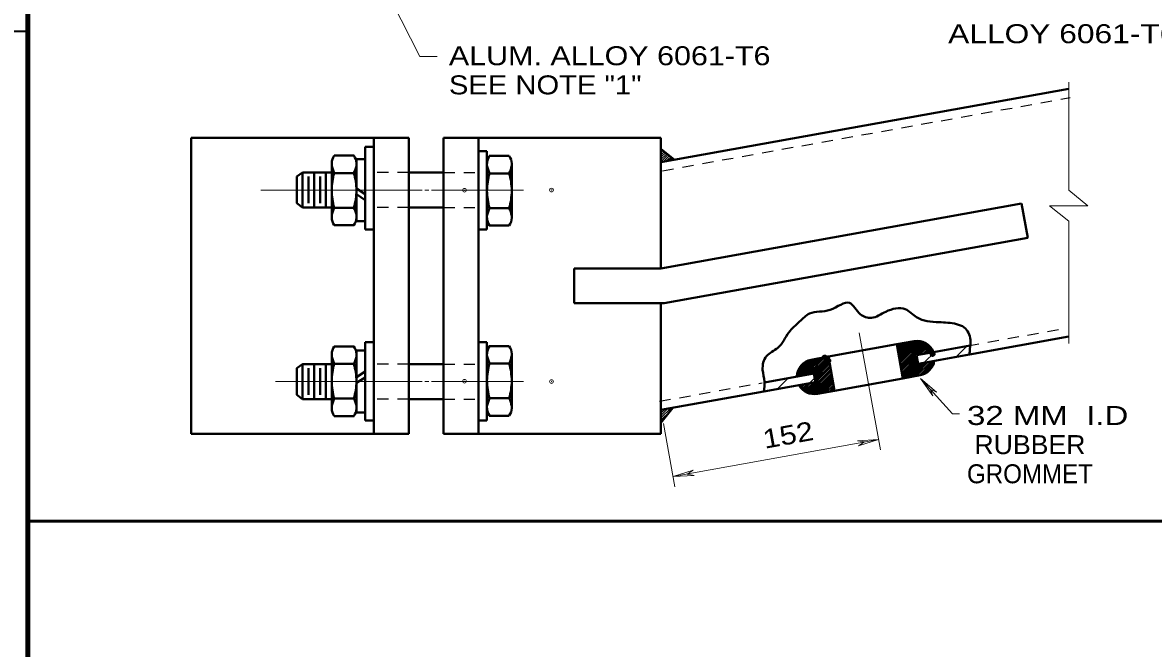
# Model space of a CAD drawing. Extents: x 312583 to 312854, y 144419 to 144597.
# Drawn here: x 312616.3 to 312661.58, y 144463.41 to 144488.46 of the extents above; entities that cross this region are included whole.
import ezdxf

# ---------------------------------------------------------------- set-up
doc = ezdxf.new("R2010")
doc.units = 0
doc.header["$LTSCALE"] = 0.3
doc.header["$PDMODE"] = 32
doc.header["$PDSIZE"] = 0.15
doc.linetypes.add('SHORT_DASHED', pattern=[2.7, 1.5, -1.2])
doc.layers.add('1', color=7, linetype='Continuous', lineweight=35)
doc.layers.add('2', color=7, linetype='Continuous', lineweight=13)

msp = doc.modelspace()

# ---------------------------------------------------------------- linework, layer by layer
at = {"layer": '1', "lineweight": 13}
for p, q in [((312658.1938, 144486.0803), (312658.1938, 144481.7486)), ((312658.1938, 144480.5066), (312658.1938, 144475.6153)), ((312652.4055, 144474.8486), (312652.8425, 144475.2856)), ((312653.6858, 144475.0786), (312654.1305, 144475.5156)), ((312646.5251, 144473.7983), (312646.9545, 144474.2276)), ((312647.8055, 144474.0206), (312648.0201, 144474.2353))]:
    msp.add_line(p, q, dxfattribs=at)
at = {"layer": '1', "lineweight": 40}
for p, q in [((312641.8638, 144482.8679), (312658.1938, 144485.8043)), ((312623.0498, 144477.9229), (312623.0498, 144483.8493)), ((312630.3638, 144477.9229), (312630.3638, 144483.8493)), ((312631.7591, 144477.9229), (312631.7591, 144483.8493)), ((312633.1545, 144476.9186), (312633.1545, 144483.8493)), ((312634.5498, 144477.9229), (312634.5498, 144483.8493)), ((312641.8638, 144478.6206), (312641.8638, 144483.8493)), ((312630.0188, 144483.4889), (312630.0188, 144480.1769)), ((312630.0188, 144483.4889), (312630.3638, 144483.4889)), ((312641.8638, 144483.4046), (312642.4081, 144482.9676)), ((312629.5741, 144483.1439), (312628.7768, 144483.1439)), ((312629.6661, 144482.8373), (312629.6661, 144482.9983)), ((312629.6661, 144482.9983), (312629.6661, 144480.5143)), ((312629.6661, 144482.9983), (312630.0188, 144482.9983)), ((312630.3638, 144483.1439), (312630.3638, 144480.3533)), ((312634.8948, 144483.3126), (312634.5498, 144483.3126)), ((312634.5498, 144480.3533), (312634.5498, 144483.1439)), ((312634.8948, 144480.1769), (312634.8948, 144483.3126)), ((312634.9868, 144483.1286), (312635.7841, 144483.1286)), ((312628.6771, 144482.4539), (312627.5118, 144482.4539)), ((312627.9795, 144482.4539), (312627.9795, 144481.7486)), ((312628.4471, 144482.4539), (312628.4471, 144481.7486)), ((312628.6771, 144482.8296), (312628.6771, 144481.7563)), ((312629.5741, 144482.4386), (312628.7768, 144482.4386)), ((312629.6661, 144482.8373), (312629.6661, 144481.7639)), ((312633.1545, 144482.4539), (312631.7591, 144482.4539)), ((312634.8948, 144482.8219), (312634.8948, 144481.7486)), ((312634.9868, 144482.4233), (312635.7841, 144482.4233)), ((312635.8838, 144482.8143), (312635.8838, 144481.7409)), ((312627.2818, 144482.2929), (312627.2818, 144481.7486)), ((312627.7495, 144482.2929), (312627.7495, 144481.7486)), ((312628.2095, 144482.2929), (312628.2095, 144481.7486)), ((312627.2818, 144481.2273), (312627.2818, 144481.7639)), ((312627.7495, 144481.2273), (312627.7495, 144481.7639)), ((312627.9795, 144481.0586), (312627.9795, 144481.7639)), ((312628.2095, 144481.2273), (312628.2095, 144481.7639)), ((312628.4471, 144481.0586), (312628.4471, 144481.7639)), ((312628.6771, 144480.6599), (312628.6771, 144481.7639)), ((312629.6661, 144481.8176), (312630.0188, 144481.5876)), ((312629.6661, 144480.6599), (312629.6661, 144481.7639)), ((312629.6661, 144481.5876), (312630.0188, 144481.3576)), ((312634.8948, 144480.6446), (312634.8948, 144481.7486)), ((312635.8838, 144480.6446), (312635.8838, 144481.7486)), ((312628.6771, 144481.0586), (312627.5118, 144481.0586)), ((312633.1545, 144481.0586), (312631.7591, 144481.0586)), ((312641.8638, 144478.6206), (312656.3078, 144481.2196)), ((312656.3078, 144481.2196), (312656.5531, 144479.8473)), ((312629.5741, 144481.0509), (312628.7768, 144481.0509)), ((312629.6661, 144480.5143), (312629.6661, 144480.6599)), ((312634.9868, 144481.0356), (312635.7841, 144481.0356)), ((312629.5741, 144480.3533), (312628.7768, 144480.3533)), ((312629.6661, 144480.5143), (312630.0188, 144480.5143)), ((312630.0188, 144480.1769), (312630.3638, 144480.1769)), ((312634.8948, 144480.1769), (312634.5498, 144480.1769)), ((312634.9868, 144480.3379), (312635.7841, 144480.3379)), ((312641.9865, 144477.2253), (312656.5531, 144479.8473)), ((312641.8638, 144478.6206), (312638.3831, 144478.6206)), ((312638.3831, 144478.6206), (312638.3831, 144477.2253)), ((312623.0498, 144477.9229), (312623.0498, 144471.9966)), ((312630.3638, 144477.9229), (312630.3638, 144471.9966)), ((312631.7591, 144477.9229), (312631.7591, 144471.9966)), ((312633.1545, 144477.9229), (312633.1545, 144471.9966)), ((312634.5498, 144477.9229), (312634.5498, 144471.9966)), ((312641.9865, 144477.2253), (312638.3831, 144477.2253)), ((312641.8638, 144477.2253), (312641.8638, 144471.9966)), ((312630.0188, 144472.5333), (312630.0188, 144475.6689)), ((312630.0188, 144475.6689), (312630.3638, 144475.6689)), ((312634.8948, 144475.6689), (312634.5498, 144475.6689)), ((312634.8948, 144475.6689), (312634.8948, 144472.5333)), ((312651.3091, 144475.5846), (312651.9991, 144475.7073)), ((312654.2148, 144475.1783), (312658.1938, 144475.8913)), ((312628.6771, 144475.1859), (312628.6771, 144474.0819)), ((312629.5741, 144475.4926), (312628.7768, 144475.4926)), ((312629.6661, 144475.3316), (312629.6661, 144475.1936)), ((312629.6661, 144475.3316), (312630.0188, 144475.3316)), ((312629.6661, 144472.8476), (312629.6661, 144475.3316)), ((312629.6661, 144475.1936), (312629.6661, 144474.0896)), ((312630.3638, 144472.7096), (312630.3638, 144475.4926)), ((312634.5498, 144475.4926), (312634.5498, 144472.7096)), ((312634.8948, 144475.2089), (312634.8948, 144474.1049)), ((312634.9868, 144475.5079), (312635.7841, 144475.5079)), ((312635.8838, 144475.2013), (312635.8838, 144474.0973)), ((312648.5721, 144475.0939), (312651.3091, 144475.5846)), ((312651.3091, 144475.5846), (312651.5545, 144474.2199)), ((312652.0988, 144475.1476), (312652.7735, 144475.2703)), ((312652.1601, 144474.8026), (312654.2148, 144475.1783)), ((312652.7735, 144475.2703), (312654.2455, 144475.5386)), ((312628.6771, 144474.7873), (312627.5118, 144474.7873)), ((312627.9795, 144474.7873), (312627.9795, 144474.0819)), ((312628.4471, 144474.7873), (312628.4471, 144474.0819)), ((312629.5741, 144474.8026), (312628.7768, 144474.8026)), ((312633.1545, 144474.7873), (312631.7591, 144474.7873)), ((312634.9868, 144474.8103), (312635.7841, 144474.8103)), ((312648.5645, 144475.0939), (312647.8821, 144474.9636)), ((312648.5721, 144475.0939), (312648.8175, 144473.7216)), ((312652.0988, 144475.1476), (312652.1601, 144474.8026)), ((312627.2818, 144474.6263), (312627.2818, 144474.0819)), ((312627.7495, 144474.6263), (312627.7495, 144474.0819)), ((312628.2095, 144474.6263), (312628.2095, 144474.0819)), ((312629.6661, 144474.2659), (312630.0188, 144474.4959)), ((312646.0115, 144474.0589), (312647.9818, 144474.4116)), ((312647.9818, 144474.4116), (312648.0508, 144474.0666)), ((312652.2445, 144474.3426), (312651.5545, 144474.2199)), ((312627.2818, 144473.5606), (312627.2818, 144474.0973)), ((312627.7495, 144473.5606), (312627.7495, 144474.0973)), ((312627.9795, 144473.3919), (312627.9795, 144474.0973)), ((312628.2095, 144473.5606), (312628.2095, 144474.0973)), ((312628.4471, 144473.3919), (312628.4471, 144474.0973)), ((312628.6771, 144473.0163), (312628.6771, 144474.0973)), ((312629.6661, 144474.0359), (312630.0188, 144474.2583)), ((312629.6661, 144473.0086), (312629.6661, 144474.0896)), ((312634.8948, 144473.0239), (312634.8948, 144474.1049)), ((312635.8838, 144473.0316), (312635.8838, 144474.1049)), ((312645.9808, 144473.6986), (312648.0508, 144474.0666)), ((312648.8175, 144473.7216), (312651.5545, 144474.2199)), ((312628.6771, 144473.3919), (312627.5118, 144473.3919)), ((312629.5741, 144473.4149), (312628.7768, 144473.4149)), ((312633.1545, 144473.3919), (312631.7591, 144473.3919)), ((312634.9868, 144473.4303), (312635.7841, 144473.4303)), ((312641.8638, 144472.9626), (312645.9808, 144473.6986)), ((312648.1275, 144473.5989), (312648.8175, 144473.7216)), ((312629.6661, 144473.0086), (312629.6661, 144472.8476)), ((312641.8638, 144472.4336), (312642.3315, 144473.0393)), ((312629.5741, 144472.7096), (312628.7768, 144472.7096)), ((312629.6661, 144472.8476), (312630.0188, 144472.8476)), ((312630.0188, 144472.5333), (312630.3638, 144472.5333)), ((312634.8948, 144472.5333), (312634.5498, 144472.5333)), ((312634.9868, 144472.7249), (312635.7841, 144472.7249))]:
    msp.add_line(p, q, dxfattribs=at)
at = {"layer": '1', "linetype": 'SHORT_DASHED', "lineweight": 25}
for p, q in [((312641.9251, 144482.5306), (312658.2551, 144485.4593)), ((312631.7591, 144482.4539), (312630.3638, 144482.4539)), ((312633.1545, 144482.4539), (312634.5498, 144482.4539)), ((312631.7591, 144481.0586), (312630.3638, 144481.0586)), ((312633.1545, 144481.0586), (312634.5498, 144481.0586)), ((312654.1535, 144475.5233), (312658.1325, 144476.2363)), ((312631.7591, 144474.7873), (312630.3638, 144474.7873)), ((312633.1545, 144474.7873), (312634.5498, 144474.7873)), ((312641.8025, 144473.2999), (312645.9195, 144474.0436)), ((312631.7591, 144473.3919), (312630.3638, 144473.3919)), ((312633.1545, 144473.3919), (312634.5498, 144473.3919))]:
    msp.add_line(p, q, dxfattribs=at)
at = {"layer": '1', "lineweight": 25}
for p, q in [((312641.8638, 144483.3433), (312641.8945, 144483.3739)), ((312641.8638, 144483.2513), (312641.9481, 144483.3356)), ((312641.8638, 144483.1593), (312642.0018, 144483.2973)), ((312641.8638, 144483.0673), (312642.0478, 144483.2513)), ((312641.8638, 144482.9753), (312642.1015, 144483.2129)), ((312641.8638, 144482.8909), (312642.1551, 144483.1746)), ((312641.9558, 144482.8833), (312642.2011, 144483.1363)), ((312642.0631, 144482.9063), (312642.2548, 144483.0903)), ((312642.1705, 144482.9293), (312642.3008, 144483.0519)), ((312642.2855, 144482.9446), (312642.3545, 144483.0136)), ((312641.8638, 144472.6406), (312642.2548, 144473.0239)), ((312641.8638, 144472.7326), (312642.1398, 144473.0086)), ((312641.8638, 144472.8246), (312642.0325, 144472.9856)), ((312641.8638, 144472.9089), (312641.9175, 144472.9703)), ((312641.8638, 144472.5486), (312642.2395, 144472.9243)), ((312641.8638, 144472.4566), (312641.9481, 144472.5409))]:
    msp.add_line(p, q, dxfattribs=at)
at = {"layer": '1'}
for p, q in [((312651.3475, 144475.3776), (312651.6081, 144475.6383)), ((312651.3628, 144475.3009), (312651.7155, 144475.6536)), ((312651.3781, 144475.2243), (312651.8305, 144475.6766)), ((312651.3935, 144475.1476), (312651.9378, 144475.6996)), ((312651.4011, 144475.0709), (312652.0451, 144475.7149)), ((312651.4165, 144474.9943), (312652.1371, 144475.7149)), ((312651.4318, 144474.9176), (312652.2215, 144475.7073)), ((312651.4471, 144474.8409), (312652.2981, 144475.6996)), ((312651.4625, 144474.7643), (312652.3671, 144475.6689)), ((312651.4778, 144474.6876), (312652.4285, 144475.6459)), ((312651.3245, 144475.5386), (312651.3858, 144475.5999)), ((312651.3321, 144475.4543), (312651.4931, 144475.6153)), ((312651.4855, 144474.6109), (312652.4898, 144475.6076)), ((312652.1218, 144475.1553), (312652.5358, 144475.5693)), ((312652.4515, 144475.2166), (312652.6815, 144475.4389)), ((312652.5665, 144475.2319), (312652.7121, 144475.3853)), ((312652.6738, 144475.2549), (312652.7505, 144475.3239)), ((312647.3071, 144474.3043), (312647.9895, 144474.9866)), ((312647.3225, 144474.4116), (312647.8745, 144474.9636)), ((312647.3608, 144474.5419), (312647.7365, 144474.9099)), ((312647.3991, 144474.3119), (312648.0968, 144475.0019)), ((312647.5141, 144474.3273), (312648.2118, 144475.0249)), ((312647.6215, 144474.3503), (312648.3191, 144475.0479)), ((312647.7365, 144474.3656), (312648.4265, 144475.0633)), ((312647.8438, 144474.3886), (312648.5415, 144475.0863)), ((312647.9511, 144474.4039), (312648.5798, 144475.0326)), ((312647.9971, 144474.3579), (312648.5951, 144474.9559)), ((312648.0125, 144474.2813), (312648.6028, 144474.8793)), ((312648.0278, 144474.2046), (312648.6181, 144474.8026)), ((312648.0431, 144474.1279), (312648.6335, 144474.7183)), ((312651.5008, 144474.5343), (312652.0988, 144475.1323)), ((312651.5161, 144474.4576), (312652.1141, 144475.0556)), ((312651.5315, 144474.3809), (312652.1295, 144474.9789)), ((312651.5468, 144474.3043), (312652.1448, 144474.9023)), ((312651.5545, 144474.2276), (312652.1601, 144474.8333)), ((312651.6541, 144474.2353), (312652.2368, 144474.8179)), ((312651.7691, 144474.2583), (312652.3518, 144474.8409)), ((312651.8765, 144474.2813), (312652.4591, 144474.8563)), ((312651.9915, 144474.2966), (312652.5665, 144474.8793)), ((312652.0988, 144474.3196), (312652.6815, 144474.8946)), ((312652.2138, 144474.3349), (312652.7888, 144474.9176)), ((312652.3365, 144474.3733), (312652.7811, 144474.8179)), ((312647.6828, 144473.6756), (312648.6411, 144474.6493)), ((312647.7365, 144473.6449), (312648.6565, 144474.5649)), ((312647.8055, 144473.6219), (312648.6718, 144474.4959)), ((312647.8745, 144473.6066), (312648.6871, 144474.4193)), ((312647.9588, 144473.5989), (312648.7025, 144474.3426)), ((312648.0431, 144473.5913), (312648.7178, 144474.2659)), ((312652.5051, 144474.4499), (312652.7045, 144474.6493)), ((312647.3991, 144473.9439), (312647.4145, 144473.9516)), ((312647.4375, 144473.8903), (312647.5218, 144473.9746)), ((312647.4758, 144473.8366), (312647.6291, 144473.9976)), ((312647.5218, 144473.7906), (312647.7441, 144474.0129)), ((312647.5678, 144473.7446), (312647.8515, 144474.0359)), ((312647.6215, 144473.7139), (312647.9665, 144474.0513)), ((312648.1505, 144473.6066), (312648.7331, 144474.1893)), ((312648.2578, 144473.6219), (312648.7485, 144474.1126)), ((312648.3651, 144473.6449), (312648.7561, 144474.0359)), ((312648.4801, 144473.6679), (312648.7715, 144473.9516)), ((312648.5951, 144473.6833), (312648.7868, 144473.8826)), ((312648.7025, 144473.7063), (312648.7945, 144473.7983)), ((312648.8098, 144473.7216), (312648.8098, 144473.7293))]:
    msp.add_line(p, q, dxfattribs=at)
at = {"layer": '1', "lineweight": 53}
msp.add_line((312718.4834, 144468.5083), (312616.5, 144468.5083), dxfattribs=at)
at = {"layer": '1', "lineweight": 158}
msp.add_lwpolyline([(312616.5, 144423.1446), (312616.5, 144585.0846), (312849, 144585.0846)], dxfattribs=at)
at = {"layer": '1'}
for points in [[(312616.5, 144456.901), (312608.8858, 144456.901), (312608.8858, 144488.1192), (312616.5, 144488.1192)], [(312652.2291, 144475.1783), (312652.5895, 144475.5309), (312652.5895, 144475.5386)], [(312652.3441, 144475.1936), (312652.6355, 144475.4849), (312652.6355, 144475.4849)]]:
    msp.add_lwpolyline(points, dxfattribs=at)
at = {"layer": '1', "lineweight": 40}
for points in [[(312623.0498, 144483.8493), (312630.3638, 144483.8493), (312631.7591, 144483.8493)], [(312641.8638, 144483.8493), (312634.5498, 144483.8493), (312633.1545, 144483.8493)], [(312627.2818, 144482.2929), (312627.5118, 144482.4539), (312627.5118, 144481.7486)], [(312627.2818, 144481.2273), (312627.5118, 144481.0586), (312627.5118, 144481.7639)], [(312627.2818, 144474.6263), (312627.5118, 144474.7873), (312627.5118, 144474.0819)], [(312627.2818, 144473.5606), (312627.5118, 144473.3919), (312627.5118, 144474.0973)], [(312623.0498, 144471.9966), (312630.3638, 144471.9966), (312631.7591, 144471.9966)], [(312641.8638, 144471.9966), (312634.5498, 144471.9966), (312633.1545, 144471.9966)]]:
    msp.add_lwpolyline(points, dxfattribs=at)
at = {"layer": '1', "lineweight": 25}
msp.add_lwpolyline([(312642.3928, 144482.9676), (312642.4005, 144482.9753), (312642.4005, 144482.9753)], dxfattribs=at)
at = {"layer": '1', "lineweight": 40}
for centre, radius, start, end in [((312629.2508, 144482.8146), 0.574, 145.8703, 178.33743), ((312629.0926, 144482.8146), 0.574, 1.66257, 34.1297), ((312635.4697, 144482.8007), 0.574, 145.8703, 178.33743), ((312635.3116, 144482.8007), 0.574, 1.66257, 34.1297), ((312630.2845, 144483.0918), 1.6437, 191.77014, 203.36365), ((312631.6409, 144481.6721), 2.9664, 164.99798, 178.595), ((312628.0588, 144483.0918), 1.6437, 336.63635, 348.22986), ((312626.7025, 144481.6721), 2.9664, 1.405, 15.00202), ((312637.8598, 144481.6582), 2.9664, 164.99798, 178.595), ((312636.5035, 144483.0778), 1.6437, 191.77014, 203.36365), ((312634.2778, 144483.0778), 1.6437, 336.63635, 348.22986), ((312632.9214, 144481.6582), 2.9664, 1.405, 15.00202), ((312631.6409, 144481.8176), 2.9664, 181.405, 195.00202), ((312626.7025, 144481.8176), 2.9664, 344.99798, 358.595), ((312637.8598, 144481.8036), 2.9664, 181.405, 195.00202), ((312632.9214, 144481.8036), 2.9664, 344.99798, 358.595), ((312630.2845, 144480.3979), 1.6437, 156.63635, 168.22986), ((312629.2508, 144480.6751), 0.574, 181.66257, 214.1297), ((312628.0588, 144480.3979), 1.6437, 11.77014, 23.36365), ((312629.0926, 144480.6751), 0.574, 325.8703, 358.33743), ((312636.5035, 144480.3839), 1.6437, 156.63635, 168.22986), ((312635.4697, 144480.6611), 0.574, 181.66257, 214.1297), ((312634.2778, 144480.3839), 1.6437, 11.77014, 23.36365), ((312635.3116, 144480.6611), 0.574, 325.8703, 358.33743), ((312652.1238, 144475.0254), 0.694, 20.92751, 100.40744), ((312629.2508, 144475.1736), 0.574, 145.8703, 178.33743), ((312629.0926, 144475.1736), 0.574, 1.66257, 34.1297), ((312635.4697, 144475.1875), 0.574, 145.8703, 178.33743), ((312635.3116, 144475.1875), 0.574, 1.66257, 34.1297), ((312630.2845, 144475.4508), 1.6437, 191.77014, 203.36365), ((312631.6409, 144474.0311), 2.9664, 164.99798, 178.595), ((312628.0588, 144475.4508), 1.6437, 336.63635, 348.22986), ((312626.7025, 144474.0311), 2.9664, 1.405, 15.00202), ((312637.8598, 144474.045), 2.9664, 164.99798, 178.595), ((312636.5035, 144475.4647), 1.6437, 191.77014, 203.36365), ((312634.2778, 144475.4647), 1.6437, 336.63635, 348.22986), ((312632.9214, 144474.045), 2.9664, 1.405, 15.00202), ((312648.0028, 144474.2835), 0.694, 99.90643, 179.34108), ((312652.1238, 144475.0254), 0.694, 279.9552, 351.41104), ((312631.6409, 144474.1766), 2.9664, 181.405, 195.00202), ((312626.7025, 144474.1766), 2.9664, 344.99798, 358.595), ((312637.8598, 144474.1905), 2.9664, 181.405, 195.00202), ((312632.9214, 144474.1905), 2.9664, 344.99798, 358.595), ((312648.0028, 144474.2835), 0.694, 208.60683, 280.45563), ((312630.2845, 144472.7569), 1.6437, 156.63635, 168.22986), ((312628.0588, 144472.7569), 1.6437, 11.77014, 23.36365), ((312636.5035, 144472.7708), 1.6437, 156.63635, 168.22986), ((312634.2778, 144472.7708), 1.6437, 11.77014, 23.36365), ((312629.2508, 144473.0341), 0.574, 181.66257, 214.1297), ((312629.0926, 144473.0341), 0.574, 325.8703, 358.33743), ((312635.4697, 144473.048), 0.574, 181.66257, 214.1297), ((312635.3116, 144473.048), 0.574, 325.8703, 358.33743)]:
    msp.add_arc(centre, radius, start, end, dxfattribs=at)
msp.add_spline([(312645.9808, 144473.6986), (312646.0115, 144474.0819), (312645.9348, 144474.5573), (312646.0881, 144475.1093), (312646.5405, 144475.4389), (312646.9851, 144476.0599), (312647.4145, 144476.4893), (312647.8131, 144476.8113), (312648.6411, 144476.9646), (312649.4155, 144477.2406), (312649.8448, 144476.7883), (312650.2895, 144476.6426), (312650.8721, 144476.8879), (312651.6465, 144476.9876), (312652.0988, 144476.6656), (312652.9958, 144476.4663), (312653.7011, 144476.3896), (312654.0001, 144476.2593), (312654.2531, 144475.7609), (312654.2378, 144475.4006), (312654.2148, 144475.1783)], degree=3, dxfattribs=at)
at = {"layer": '1'}
for p in [(312652.7428, 144475.1859), (312648.4265, 144475.0633), (312648.4725, 144475.0173), (312648.5185, 144474.9713), (312648.5645, 144474.9253)]:
    msp.add_point(p, dxfattribs=at)
at = {"layer": '2'}
for p, q in [((312631.0845, 144489.3003), (312632.2013, 144487.1064)), ((312632.2013, 144487.1064), (312632.899, 144487.1064)), ((312632.3035, 144481.7563), (312625.8405, 144481.7563)), ((312632.4108, 144481.7563), (312632.5718, 144481.7563)), ((312632.6791, 144481.7563), (312636.3591, 144481.7563)), ((312649.8065, 144476.0446), (312650.6498, 144471.3526)), ((312632.3035, 144474.0896), (312626.4308, 144474.0896)), ((312632.4108, 144474.0896), (312632.5718, 144474.0896)), ((312632.6791, 144474.0896), (312636.3591, 144474.0896)), ((312652.2598, 144474.2123), (312652.7505, 144473.5223)), ((312652.2598, 144474.2123), (312652.9038, 144473.6603)), ((312652.7505, 144473.5223), (312652.6431, 144473.7906)), ((312652.9038, 144473.6603), (312652.6431, 144473.7906)), ((312641.9635, 144472.4106), (312642.4158, 144469.8729)), ((312642.3468, 144470.2869), (312650.5731, 144471.7743)), ((312650.5731, 144471.7743), (312649.7298, 144471.7206)), ((312649.7298, 144471.7206), (312650.0135, 144471.6746)), ((312650.5731, 144471.7743), (312649.7681, 144471.5213)), ((312649.7681, 144471.5213), (312650.0135, 144471.6746)), ((312642.3468, 144470.2869), (312643.1518, 144470.5399)), ((312642.3468, 144470.2869), (312643.1901, 144470.3329)), ((312643.1518, 144470.5399), (312642.9065, 144470.3866)), ((312643.1901, 144470.3329), (312642.9065, 144470.3866))]:
    msp.add_line(p, q, dxfattribs=at)
for points in [[(312658.1938, 144480.5066), (312657.4195, 144481.1199), (312658.9605, 144481.1199), (312658.1938, 144481.7486)], [(312652.2598, 144474.2123), (312653.5401, 144472.7939), (312653.8246, 144472.7939)]]:
    msp.add_lwpolyline(points, dxfattribs=at)
for p in [(312633.9978, 144481.7486), (312637.4785, 144481.7563), (312633.9978, 144474.1049), (312637.4785, 144474.0896)]:
    msp.add_point(p, dxfattribs=at)

# ---------------------------------------------------------------- texts
for s, width, p in [('ALLOY 6061-T6 OR 6063-T6', 1.25, (312653.3638, 144487.6346)), ('ALUM. ALLOY 6061-T6', 1.2, (312633.3694, 144486.7527)), ('SEE NOTE "1"', 1.15, (312633.3694, 144485.5864)), ('32 MM  I.D', 1.3, (312654.1196, 144472.3525)), (' RUBBER', 1.05, (312654.1196, 144471.1862)), ('GROMMET', 0.95, (312654.1196, 144470.0199))]:
    msp.add_text(s, height=0.76, dxfattribs=dict(at, width=width)).set_placement(p)
at = {"layer": '2', "width": 1.2}
msp.add_text('152 ', height=0.76, rotation=10.29, dxfattribs=at).set_placement((312646.0189, 144471.3992))

doc.saveas('drawing.dxf')
